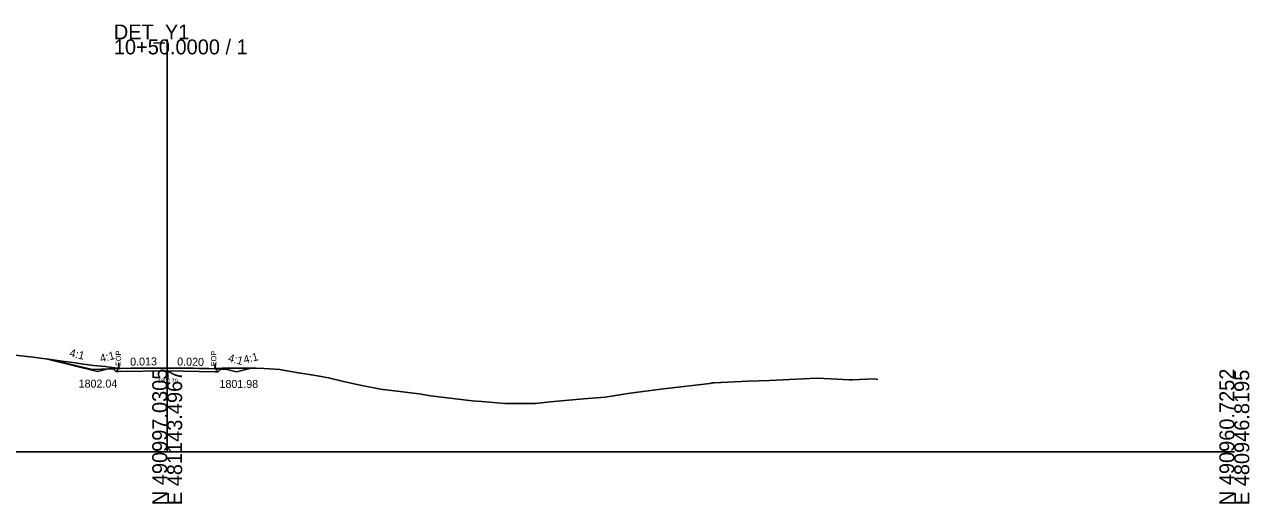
# Model space of a CAD drawing. Extents: x -26 to 403, y -10 to 3149.
# Drawn here: x 173.3 to 402.8, y 490.3 to 580.1 of the extents above; entities that cross this region are included whole.
import ezdxf

# ---------------------------------------------------------------- set-up
doc = ezdxf.new("R2010")
doc.units = 0
for name, color, linetype in [('Exist Cross Section Cell', 7, 'Continuous'), ('Exist XS Center Line Elevation Label', 7, 'Continuous'), ('Exist XS Ground Line', 7, 'Continuous'), ('Prop XS Ditch Slope Text', 7, 'Continuous'), ('Prop XS Ditch Standard Text', 7, 'Continuous'), ('Prop XS Dump Level', 7, 'Continuous'), ('Prop XS EOT Tick Mark', 7, 'Continuous'), ('Prop XS Finish Grade', 7, 'Continuous'), ('Prop XS Finish Grade Earthwork', 7, 'Continuous'), ('Prop XS Finish Grade Pavement', 7, 'Continuous'), ('Prop XS Pvmt Edge Slope', 7, 'Continuous'), ('Prop XS SE Text', 7, 'Continuous'), ('Prop XS Side Slope Text', 7, 'Continuous'), ('Prop XS Subgrade Earthwork', 7, 'Continuous'), ('Scratch_Level_3', 7, 'Continuous'), ('Scratch_Level_4', 7, 'Continuous')]:
    doc.layers.add(name, color=color, linetype=linetype)

msp = doc.modelspace()

# ---------------------------------------------------------------- linework, layer by layer
at = {"layer": 'Exist Cross Section Cell'}
for p, q in [((200, 500), (200, 577.34)), ((0, 500), (200, 500)), ((200, 500), (400, 500))]:
    msp.add_line(p, q, dxfattribs=at)
at = {"layer": 'Exist XS Ground Line'}
msp.add_lwpolyline([(163.16, 519.06), (174.9, 517.78), (176.18, 517.58), (177.75, 517.37), (178.6, 517.26), (180.74, 516.97), (181.38, 516.88), (182.77, 516.66), (183.85, 516.5), (186.2, 516.21), (186.94, 516.14), (188.42, 515.98), (188.74, 515.96), (190.72, 515.68), (190.87, 515.6), (191.26, 515.63), (193.19, 515.67), (193.82, 515.68), (196.57, 515.68), (198.89, 515.69), (199.7, 515.7), (200, 515.7), (201.42, 515.7), (202.53, 515.7), (203.95, 515.69), (204.93, 515.67), (206.49, 515.64), (207.82, 515.6), (208.71, 515.57), (209.04, 515.62), (210.31, 515.66), (210.7, 515.67), (211.84, 515.7), (214.13, 515.7), (215.69, 515.68), (216.69, 515.66), (218.13, 515.6), (219.2, 515.57), (221.09, 515.44), (222.1, 515.23), (223.18, 515.05), (224.58, 514.81), (227.82, 514.29), (230.26, 513.89), (233.07, 513.2), (236.18, 512.53), (239.96, 511.78), (247.23, 510.88), (249.37, 510.49), (257.14, 509.58), (258.98, 509.42), (263.26, 509.08), (264.27, 509.04), (268.05, 509.06), (269.03, 509.08), (271.76, 509.35), (278, 509.92), (280.46, 510.1), (282.06, 510.23), (286.77, 510.98), (293.02, 511.84), (301.67, 512.84), (302.16, 512.91), (302.53, 512.97), (308.9, 513.26), (312.86, 513.4), (321.66, 513.81), (324.35, 513.72), (327.85, 513.5), (328.37, 513.48), (332.58, 513.66), (333.2, 513.59)], dxfattribs=at)
at = {"layer": 'Prop XS Dump Level'}
for p, q in [((200, 515.74), (190.96, 515.62)), ((208.97, 515.56), (200, 515.74))]:
    msp.add_line(p, q, dxfattribs=at)
at = {"layer": 'Prop XS EOT Tick Mark'}
for p, q in [((190.96, 515.62), (190.96, 516.62)), ((208.97, 515.56), (208.97, 516.56))]:
    msp.add_line(p, q, dxfattribs=at)
at = {"layer": 'Prop XS Finish Grade'}
for p, q in [((190.96, 515.62), (189.87, 515.58)), ((208.97, 515.56), (210.06, 515.52))]:
    msp.add_line(p, q, dxfattribs=at)
at = {"layer": 'Prop XS Finish Grade Earthwork'}
for p, q in [((186.96, 515.04), (177.55, 517.39)), ((188.96, 515.54), (186.96, 515.04)), ((188.96, 515.54), (189.87, 515.58)), ((210.06, 515.52), (210.97, 515.48)), ((210.97, 515.48), (212.97, 514.98)), ((212.97, 514.98), (215.77, 515.68))]:
    msp.add_line(p, q, dxfattribs=at)
at = {"layer": 'Prop XS Finish Grade Pavement'}
for p, q in [((190.96, 515.62), (200, 515.74)), ((200, 515.74), (208.97, 515.56))]:
    msp.add_line(p, q, dxfattribs=at)
at = {"layer": 'Prop XS Pvmt Edge Slope'}
for p, q in [((190.96, 515.62), (190.39, 515.06)), ((208.97, 515.56), (209.54, 515))]:
    msp.add_line(p, q, dxfattribs=at)
at = {"layer": 'Prop XS Subgrade Earthwork'}
for p, q in [((190.39, 515.06), (189.87, 515.58)), ((190.96, 515.08), (190.39, 515.06)), ((200, 515.2), (190.96, 515.08)), ((208.97, 515.02), (200, 515.2)), ((208.97, 515.02), (209.54, 515)), ((209.54, 515), (210.06, 515.52))]:
    msp.add_line(p, q, dxfattribs=at)
at = {"layer": 'Scratch_Level_3'}
for p in [(178.06, 517.33), (190.96, 515.62)]:
    msp.add_line(p, (185.96, 515.42), dxfattribs=at)
at = {"layer": 'Scratch_Level_4'}
for p, q in [((186.96, 515.04), (177.55, 517.39)), ((188.96, 515.54), (186.96, 515.04)), ((188.96, 515.54), (189.87, 515.58)), ((190.96, 515.62), (189.87, 515.58)), ((190.96, 515.62), (200, 515.74)), ((200, 515.74), (208.97, 515.56)), ((208.97, 515.56), (210.06, 515.52)), ((210.06, 515.52), (210.97, 515.48)), ((210.97, 515.48), (212.97, 514.98)), ((212.97, 514.98), (215.77, 515.68))]:
    msp.add_line(p, q, dxfattribs=at)

# ---------------------------------------------------------------- texts
at = {"layer": 'Exist Cross Section Cell'}
for s, p in [('DET_Y1', (190, 577.34)), ('10+50.0000 / 1', (190, 574.54))]:
    msp.add_text(s, height=2.8, dxfattribs=at).set_placement(p)
for s, p in [('N 490997.0305', (200, 490)), ('E 481143.4967', (202.8, 490)), ('N 490960.7252', (400, 490)), ('E 480946.8195', (402.8, 490))]:
    msp.add_text(s, height=2.8, rotation=90, dxfattribs=at).set_placement(p)
at = {"layer": 'Exist XS Center Line Elevation Label'}
msp.add_text('1802.70', height=0.75, dxfattribs=at).set_placement((198.24, 512.95))
at = {"layer": 'Prop XS Ditch Slope Text'}
for rotation, p in [(14.0362, (187.59, 516.75)), (345.9638, (211.31, 516.94))]:
    msp.add_text('4:1', height=1.5, rotation=rotation, dxfattribs=at).set_placement(p)
at = {"layer": 'Prop XS Ditch Standard Text'}
for s, p in [('1802.04', (183.4, 512.04)), ('1801.98', (209.8, 511.98))]:
    msp.add_text(s, height=1.5, dxfattribs=at).set_placement(p)
at = {"layer": 'Prop XS SE Text'}
for s, rotation, p in [('0.013', 0.7646, (193.07, 516.15)), ('0.020', 358.8351, (201.86, 516.2))]:
    msp.add_text(s, height=1.5, rotation=rotation, dxfattribs=at).set_placement(p)
at = {"layer": 'Prop XS Side Slope Text'}
for rotation, p in [(345.9638, (181.58, 517.93)), (14.0362, (214.49, 516.53))]:
    msp.add_text('4:1', height=1.5, rotation=rotation, dxfattribs=at).set_placement(p)
at = {"layer": 'Scratch_Level_3'}
for p in [(191.37, 515.62), (209.21, 515.57)]:
    msp.add_text('-EOP', height=1, rotation=90, dxfattribs=at).set_placement(p)

doc.saveas('drawing.dxf')
